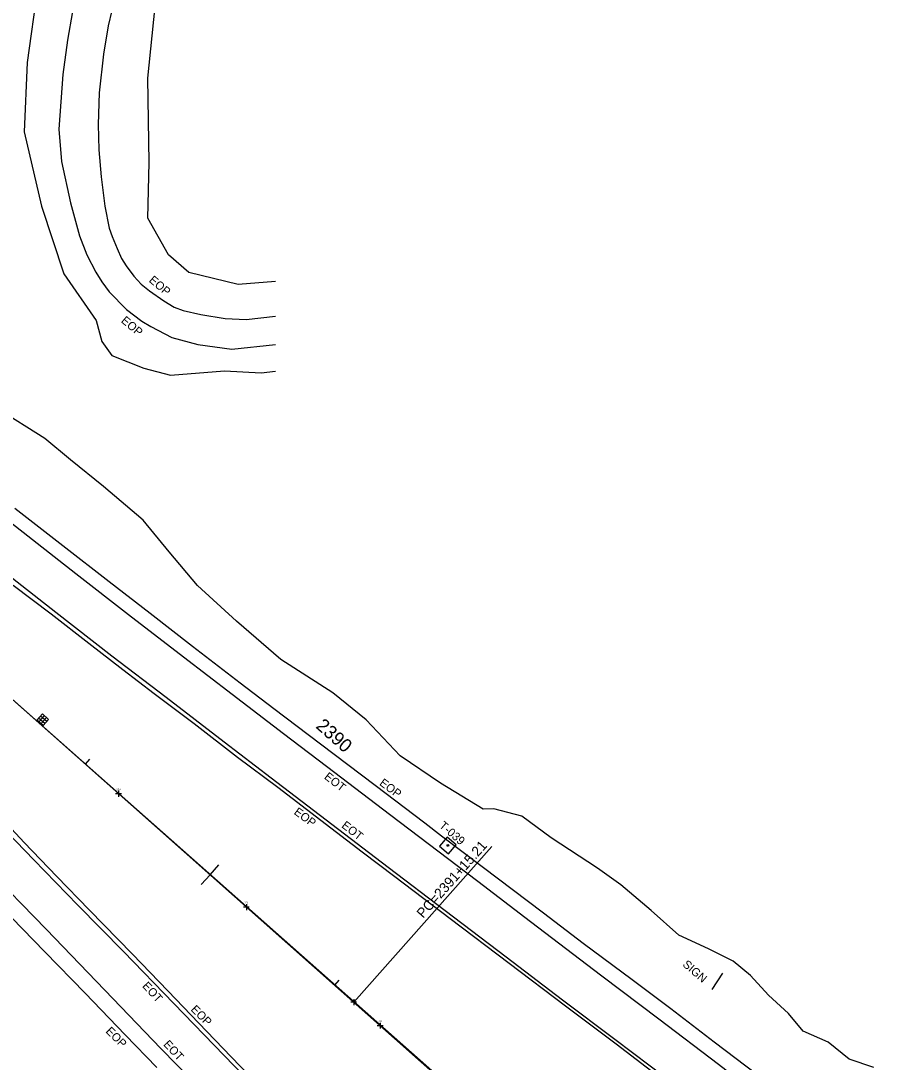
# Model space of a CAD drawing. Extents: x 2076109 to 2080761, y 592812 to 596750.
# Drawn here: x 2077729 to 2078257, y 595198 to 595823 of the extents above; entities that cross this region are included whole.
import ezdxf

# ---------------------------------------------------------------- set-up
doc = ezdxf.new("R2010")
doc.units = 0
for name, color, linetype in [('Default', 7, 'Continuous'), ('RD_EX_BldgApp', 7, 'Continuous'), ('RD_EX_BldgApp_txCode', 7, 'Continuous'), ('RD_EX_DR_Inlet', 7, 'Continuous'), ('RD_EX_Misc', 7, 'Continuous'), ('RD_EX_Misc_txCode', 7, 'Continuous'), ('RD_EX_Road', 7, 'Continuous'), ('RD_EX_Road_txCode', 7, 'Continuous'), ('RD_EX_VEG', 7, 'Continuous'), ('RD_HC_Cl', 7, 'Continuous'), ('RD_HC_Data', 7, 'Continuous'), ('RD_HC_Data_Tic', 7, 'Continuous'), ('RD_HC_Survey', 7, 'Continuous'), ('RD_HC_Survey_txCode', 7, 'Continuous'), ('RD_HC_TX_Sta50', 7, 'Continuous')]:
    doc.layers.add(name, color=color, linetype=linetype)

msp = doc.modelspace()

# ---------------------------------------------------------------- linework, layer by layer
at = {"layer": 'Default'}
for p, q in [((2077364.31, 595733.06), (2078453.96, 594769.07)), ((2077364.31, 595733.06), (2078453.96, 594769.07)), ((2077404.89, 595698.18), (2078420.27, 594797.03)), ((2077404.89, 595698.18), (2078420.27, 594797.03)), ((2077789.04, 595358.59), (2077785.54, 595358.59)), ((2077789.04, 595358.59), (2077785.54, 595358.59)), ((2077787.29, 595360.34), (2077787.29, 595356.84)), ((2077787.29, 595360.34), (2077787.29, 595356.84)), ((2077865.75, 595290.59), (2077862.25, 595290.59)), ((2077865.75, 595290.59), (2077862.25, 595290.59)), ((2077864, 595292.34), (2077864, 595288.84)), ((2077864, 595292.34), (2077864, 595288.84)), ((2077930.13, 595233.58), (2077926.63, 595233.58)), ((2077930.13, 595233.58), (2077926.63, 595233.58)), ((2077928.38, 595235.33), (2077928.38, 595231.83)), ((2077928.38, 595235.33), (2077928.38, 595231.83)), ((2077944.24, 595221.17), (2077944.24, 595217.67)), ((2077944.24, 595221.17), (2077944.24, 595217.67)), ((2077945.99, 595219.42), (2077942.49, 595219.42)), ((2077945.99, 595219.42), (2077942.49, 595219.42))]:
    msp.add_line(p, q, dxfattribs=at)
msp.add_arc((2104218.85, 624856.19), 39606.66, 228.410497, 230.313125, dxfattribs=at)
msp.add_arc((2104218.85, 624856.19), 39606.66, 228.410497, 230.313125, dxfattribs=at)
at = {"layer": 'RD_EX_BldgApp'}
msp.add_line((2078149.53, 595250.98), (2078143.14, 595241.23), dxfattribs=at)
msp.add_line((2078149.53, 595250.98), (2078143.14, 595241.23), dxfattribs=at)
at = {"layer": 'RD_EX_DR_Inlet'}
for p, q in [((2077743.08, 595400.72), (2077739.35, 595404.06)), ((2077743.08, 595400.72), (2077739.35, 595404.06)), ((2077742.81, 595405.53), (2077739.48, 595401.8)), ((2077742.81, 595405.53), (2077739.48, 595401.8)), ((2077744.21, 595401.99), (2077740.48, 595405.32)), ((2077744.21, 595401.99), (2077740.48, 595405.32)), ((2077744.08, 595404.39), (2077740.74, 595400.66)), ((2077744.08, 595404.39), (2077740.74, 595400.66))]:
    msp.add_line(p, q, dxfattribs=at)
msp.add_lwpolyline([(2077741.61, 595406.59), (2077745.34, 595403.26), (2077742.01, 595399.53), (2077738.28, 595402.86)], close=True, dxfattribs=at)
msp.add_lwpolyline([(2077741.61, 595406.59), (2077745.34, 595403.26), (2077742.01, 595399.53), (2077738.28, 595402.86)], close=True, dxfattribs=at)
at = {"layer": 'RD_EX_Misc'}
for points in [[(2077949.74, 595346.22), (2077917.12, 595371.24), (2077886.25, 595394.66), (2077855.54, 595418.26), (2077826.17, 595440.63), (2077793.37, 595466.01), (2077761.67, 595490.62), (2077722.71, 595521.26), (2077691.23, 595545.97), (2077665.74, 595566.25), (2077632.03, 595593.21), (2077582.35, 595633.88), (2077560.53, 595652.07), (2077526.26, 595680.98), (2077495.89, 595706.68), (2077469.6, 595728.93), (2077440.39, 595753.88), (2077413.8, 595776.66), (2077390.58, 595796.7)], [(2077949.74, 595346.22), (2077917.12, 595371.24), (2077886.25, 595394.66), (2077855.54, 595418.26), (2077826.17, 595440.63), (2077793.37, 595466.01), (2077761.67, 595490.62), (2077722.71, 595521.26), (2077691.23, 595545.97), (2077665.74, 595566.25), (2077632.03, 595593.21), (2077582.35, 595633.88), (2077560.53, 595652.07), (2077526.26, 595680.98), (2077495.89, 595706.68), (2077469.6, 595728.93), (2077440.39, 595753.88), (2077413.8, 595776.66), (2077390.58, 595796.7)], [(2077362.93, 595786.89), (2077392.15, 595761.97), (2077424.77, 595734), (2077441.81, 595719.44), (2077465.76, 595699.03), (2077496.26, 595672.94), (2077521.85, 595651.48), (2077549.58, 595628.1), (2077573.59, 595607.87), (2077599.85, 595586.33), (2077627.21, 595563.92), (2077661.18, 595537.05), (2077689.72, 595514.51), (2077716.09, 595493.76), (2077749.65, 595467.6), (2077783.36, 595441.51), (2077815.88, 595416.61), (2077850.74, 595389.82), (2077878.87, 595368.26), (2077915.16, 595340.49), (2077948.94, 595314.49)], [(2077362.93, 595786.89), (2077392.15, 595761.97), (2077424.77, 595734), (2077441.81, 595719.44), (2077465.76, 595699.03), (2077496.26, 595672.94), (2077521.85, 595651.48), (2077549.58, 595628.1), (2077573.59, 595607.87), (2077599.85, 595586.33), (2077627.21, 595563.92), (2077661.18, 595537.05), (2077689.72, 595514.51), (2077716.09, 595493.76), (2077749.65, 595467.6), (2077783.36, 595441.51), (2077815.88, 595416.61), (2077850.74, 595389.82), (2077878.87, 595368.26), (2077915.16, 595340.49), (2077948.94, 595314.49)], [(2077850.7, 595201.63), (2077820.53, 595232.8), (2077790.22, 595263.88), (2077762.8, 595291.76), (2077736.42, 595318.96), (2077709.92, 595346.36), (2077678.72, 595378.46), (2077649.91, 595408.22), (2077612.46, 595446.3), (2077577.19, 595481.07), (2077550.3, 595507.41), (2077509.12, 595546.77), (2077481.37, 595572.73), (2077443, 595608.1), (2077400.67, 595646.86), (2077373.88, 595670.82), (2077334.03, 595706.37), (2077304.56, 595732)], [(2077850.7, 595201.63), (2077820.53, 595232.8), (2077790.22, 595263.88), (2077762.8, 595291.76), (2077736.42, 595318.96), (2077709.92, 595346.36), (2077678.72, 595378.46), (2077649.91, 595408.22), (2077612.46, 595446.3), (2077577.19, 595481.07), (2077550.3, 595507.41), (2077509.12, 595546.77), (2077481.37, 595572.73), (2077443, 595608.1), (2077400.67, 595646.86), (2077373.88, 595670.82), (2077334.03, 595706.37), (2077304.56, 595732)], [(2077812.69, 595205.74), (2077779.15, 595240.73), (2077743.86, 595277.34), (2077707.16, 595314.93), (2077677.78, 595345.17), (2077641.95, 595381.51), (2077607.57, 595416.21), (2077570.67, 595452.82), (2077540.71, 595482.36), (2077500.4, 595521.29), (2077469.88, 595550.44), (2077431.8, 595585.6), (2077401.7, 595612.91), (2077373.73, 595637.96), (2077342.22, 595666.06), (2077323.28, 595683.05), (2077307.69, 595696.83), (2077294.47, 595708.58)], [(2077812.69, 595205.74), (2077779.15, 595240.73), (2077743.86, 595277.34), (2077707.16, 595314.93), (2077677.78, 595345.17), (2077641.95, 595381.51), (2077607.57, 595416.21), (2077570.67, 595452.82), (2077540.71, 595482.36), (2077500.4, 595521.29), (2077469.88, 595550.44), (2077431.8, 595585.6), (2077401.7, 595612.91), (2077373.73, 595637.96), (2077342.22, 595666.06), (2077323.28, 595683.05), (2077307.69, 595696.83), (2077294.47, 595708.58)], [(2078547.92, 594865.99), (2078523.55, 594887.48), (2078492.6, 594914.58), (2078461.72, 594941.03), (2078442.57, 594957.36), (2078414.55, 594981.01), (2078378.82, 595010.71), (2078326.85, 595053.48), (2078303.99, 595072.33), (2078272.31, 595097.98), (2078239.48, 595124.07), (2078206.94, 595149.86), (2078177.28, 595172.92), (2078147.14, 595196.07), (2078111.31, 595223.33), (2078077.15, 595249.21), (2078034.45, 595281.85), (2078002.89, 595305.93), (2077949.74, 595346.22)], [(2078547.92, 594865.99), (2078523.55, 594887.48), (2078492.6, 594914.58), (2078461.72, 594941.03), (2078442.57, 594957.36), (2078414.55, 594981.01), (2078378.82, 595010.71), (2078326.85, 595053.48), (2078303.99, 595072.33), (2078272.31, 595097.98), (2078239.48, 595124.07), (2078206.94, 595149.86), (2078177.28, 595172.92), (2078147.14, 595196.07), (2078111.31, 595223.33), (2078077.15, 595249.21), (2078034.45, 595281.85), (2078002.89, 595305.93), (2077949.74, 595346.22)], [(2077948.94, 595314.49), (2077983.17, 595288.64), (2078019.77, 595260.72), (2078053.66, 595234.89), (2078085.02, 595211.3), (2078116.87, 595187.29), (2078148.23, 595163.42), (2078181.8, 595137.39), (2078217.02, 595109.84), (2078246.55, 595086.19), (2078275.57, 595062.75), (2078305.1, 595038.73), (2078327.94, 595020.19), (2078351.12, 595001.07), (2078383.9, 594974.11), (2078414.8, 594947.69), (2078445.52, 594921.98), (2078475.27, 594896.22), (2078506.67, 594868.78), (2078527.36, 594850.61)], [(2077948.94, 595314.49), (2077983.17, 595288.64), (2078019.77, 595260.72), (2078053.66, 595234.89), (2078085.02, 595211.3), (2078116.87, 595187.29), (2078148.23, 595163.42), (2078181.8, 595137.39), (2078217.02, 595109.84), (2078246.55, 595086.19), (2078275.57, 595062.75), (2078305.1, 595038.73), (2078327.94, 595020.19), (2078351.12, 595001.07), (2078383.9, 594974.11), (2078414.8, 594947.69), (2078445.52, 594921.98), (2078475.27, 594896.22), (2078506.67, 594868.78), (2078527.36, 594850.61)], [(2077812.69, 595205.74), (2077860.4, 595156.88), (2077885.59, 595131.05), (2077918.9, 595096.93), (2077951.97, 595063.28), (2077986.45, 595028.54), (2078017.36, 594997.38), (2078046.97, 594968.42), (2078082.15, 594934.23), (2078115.46, 594902.77), (2078149.86, 594870.52), (2078195.91, 594828.19), (2078230.53, 594797.18), (2078270.78, 594762.03), (2078303.08, 594733.97), (2078349.76, 594694.22), (2078384.22, 594665.44)], [(2077812.69, 595205.74), (2077860.4, 595156.88), (2077885.59, 595131.05), (2077918.9, 595096.93), (2077951.97, 595063.28), (2077986.45, 595028.54), (2078017.36, 594997.38), (2078046.97, 594968.42), (2078082.15, 594934.23), (2078115.46, 594902.77), (2078149.86, 594870.52), (2078195.91, 594828.19), (2078230.53, 594797.18), (2078270.78, 594762.03), (2078303.08, 594733.97), (2078349.76, 594694.22), (2078384.22, 594665.44)], [(2078402.59, 594681.19), (2078376.88, 594702.6), (2078348.66, 594726.55), (2078315.84, 594754.87), (2078280.23, 594785.85), (2078257.02, 594806.28), (2078229.05, 594831.44), (2078194.83, 594862.11), (2078171.35, 594883.78), (2078139.88, 594913.53), (2078105.56, 594945.66), (2078078.38, 594971.9), (2078052.44, 594997.28), (2078024.89, 595024.02), (2077994.25, 595054.58), (2077968.94, 595080.1), (2077943.23, 595106.24), (2077919, 595131.04), (2077898.15, 595152.63), (2077868.92, 595182.73), (2077850.7, 595201.63)], [(2078402.59, 594681.19), (2078376.88, 594702.6), (2078348.66, 594726.55), (2078315.84, 594754.87), (2078280.23, 594785.85), (2078257.02, 594806.28), (2078229.05, 594831.44), (2078194.83, 594862.11), (2078171.35, 594883.78), (2078139.88, 594913.53), (2078105.56, 594945.66), (2078078.38, 594971.9), (2078052.44, 594997.28), (2078024.89, 595024.02), (2077994.25, 595054.58), (2077968.94, 595080.1), (2077943.23, 595106.24), (2077919, 595131.04), (2077898.15, 595152.63), (2077868.92, 595182.73), (2077850.7, 595201.63)]]:
    msp.add_lwpolyline(points, dxfattribs=at)
at = {"layer": 'RD_EX_Road'}
for points in [[(2077785.39, 595838.15), (2077781.1, 595819.63), (2077778.3, 595802.52), (2077775.75, 595779.35), (2077774.99, 595760.42), (2077775.46, 595745.15), (2077776.85, 595728.99), (2077779.01, 595711.45), (2077781.76, 595698.18), (2077783.47, 595693.15), (2077786.42, 595685.88), (2077789.1, 595679.93), (2077791.9, 595675.63), (2077796.45, 595669.39), (2077800.88, 595664.63), (2077805.85, 595660.61), (2077814.52, 595654.46), (2077820.76, 595650.75), (2077826.1, 595648.71), (2077836.65, 595646.4), (2077851.2, 595643.83), (2077863.79, 595643.28), (2077881.43, 595645.33)], [(2077785.39, 595838.15), (2077781.1, 595819.63), (2077778.3, 595802.52), (2077775.75, 595779.35), (2077774.99, 595760.42), (2077775.46, 595745.15), (2077776.85, 595728.99), (2077779.01, 595711.45), (2077781.76, 595698.18), (2077783.47, 595693.15), (2077786.42, 595685.88), (2077789.1, 595679.93), (2077791.9, 595675.63), (2077796.45, 595669.39), (2077800.88, 595664.63), (2077805.85, 595660.61), (2077814.52, 595654.46), (2077820.76, 595650.75), (2077826.1, 595648.71), (2077836.65, 595646.4), (2077851.2, 595643.83), (2077863.79, 595643.28), (2077881.43, 595645.33)], [(2077759.66, 595828.2), (2077756.72, 595810.93), (2077753.84, 595790.48), (2077751.51, 595757.53), (2077753.08, 595738.1), (2077758.38, 595713.3), (2077763.95, 595693.6), (2077768.24, 595682.16), (2077773.69, 595671.66), (2077777.2, 595665.93), (2077781.64, 595659.88), (2077792.03, 595649.24), (2077801.18, 595642.24), (2077806.57, 595639.05), (2077819.17, 595632.43), (2077834.77, 595628.29), (2077855.2, 595625.52), (2077881.39, 595628.28)], [(2077759.66, 595828.2), (2077756.72, 595810.93), (2077753.84, 595790.48), (2077751.51, 595757.53), (2077753.08, 595738.1), (2077758.38, 595713.3), (2077763.95, 595693.6), (2077768.24, 595682.16), (2077773.69, 595671.66), (2077777.2, 595665.93), (2077781.64, 595659.88), (2077792.03, 595649.24), (2077801.18, 595642.24), (2077806.57, 595639.05), (2077819.17, 595632.43), (2077834.77, 595628.29), (2077855.2, 595625.52), (2077881.39, 595628.28)], [(2077970.95, 595340.99), (2077941.15, 595363.54), (2077908.39, 595388.37), (2077880.38, 595409.68), (2077860.33, 595425.09), (2077831.72, 595447.1), (2077806.21, 595466.75), (2077781.68, 595485.77), (2077753.88, 595507.5), (2077725.13, 595529.95)], [(2077970.95, 595340.99), (2077941.15, 595363.54), (2077908.39, 595388.37), (2077880.38, 595409.68), (2077860.33, 595425.09), (2077831.72, 595447.1), (2077806.21, 595466.75), (2077781.68, 595485.77), (2077753.88, 595507.5), (2077725.13, 595529.95)], [(2077724.01, 595483.86), (2077746.81, 595466.67), (2077769.51, 595448.94), (2077789.94, 595433.21), (2077808.71, 595418.8), (2077832.68, 595400.85), (2077858.69, 595380.59), (2077882.81, 595362.61), (2077908.59, 595342.88), (2077933.38, 595323.73), (2077952.98, 595309.03)], [(2077724.01, 595483.86), (2077746.81, 595466.67), (2077769.51, 595448.94), (2077789.94, 595433.21), (2077808.71, 595418.8), (2077832.68, 595400.85), (2077858.69, 595380.59), (2077882.81, 595362.61), (2077908.59, 595342.88), (2077933.38, 595323.73), (2077952.98, 595309.03)], [(2077854.91, 595200.66), (2077835.52, 595221.02), (2077816.84, 595240.33), (2077795.72, 595262.34), (2077769.68, 595288.92), (2077750.23, 595309.06), (2077730.76, 595329.44), (2077715.27, 595345.72)], [(2077854.91, 595200.66), (2077835.52, 595221.02), (2077816.84, 595240.33), (2077795.72, 595262.34), (2077769.68, 595288.92), (2077750.23, 595309.06), (2077730.76, 595329.44), (2077715.27, 595345.72)], [(2078558.22, 594869.34), (2078530.91, 594893.2), (2078521.67, 594901.52), (2078497.33, 594922.45), (2078478.18, 594939.06), (2078452.82, 594960.76), (2078430.65, 594979.76), (2078394.66, 595009.49), (2078368.3, 595031.41), (2078336.81, 595057.13), (2078304.21, 595083.71), (2078270.36, 595111.03), (2078240.97, 595134.51), (2078202.89, 595164.59), (2078170.15, 595190.09), (2078144.69, 595209.49), (2078118.53, 595229.54), (2078095.36, 595247.04), (2078066.11, 595268.74), (2078042.16, 595286.91), (2078005.38, 595314.83), (2077980.94, 595333.23), (2077970.95, 595340.99)], [(2078558.22, 594869.34), (2078530.91, 594893.2), (2078521.67, 594901.52), (2078497.33, 594922.45), (2078478.18, 594939.06), (2078452.82, 594960.76), (2078430.65, 594979.76), (2078394.66, 595009.49), (2078368.3, 595031.41), (2078336.81, 595057.13), (2078304.21, 595083.71), (2078270.36, 595111.03), (2078240.97, 595134.51), (2078202.89, 595164.59), (2078170.15, 595190.09), (2078144.69, 595209.49), (2078118.53, 595229.54), (2078095.36, 595247.04), (2078066.11, 595268.74), (2078042.16, 595286.91), (2078005.38, 595314.83), (2077980.94, 595333.23), (2077970.95, 595340.99)], [(2077952.98, 595309.03), (2077986.31, 595283.86), (2078021.67, 595256.91), (2078055.44, 595231.27), (2078085.91, 595208.57), (2078127.78, 595176.36), (2078162.35, 595149.71), (2078195.51, 595123.85), (2078224.64, 595100.6), (2078250.87, 595079.67), (2078280.9, 595055.74), (2078317.56, 595025.94), (2078349.29, 594999.96), (2078375.78, 594977.71), (2078405, 594953.04), (2078440.35, 594923.16), (2078465.28, 594901.73), (2078507.59, 594865.01), (2078528.26, 594846.85)], [(2077952.98, 595309.03), (2077986.31, 595283.86), (2078021.67, 595256.91), (2078055.44, 595231.27), (2078085.91, 595208.57), (2078127.78, 595176.36), (2078162.35, 595149.71), (2078195.51, 595123.85), (2078224.64, 595100.6), (2078250.87, 595079.67), (2078280.9, 595055.74), (2078317.56, 595025.94), (2078349.29, 594999.96), (2078375.78, 594977.71), (2078405, 594953.04), (2078440.35, 594923.16), (2078465.28, 594901.73), (2078507.59, 594865.01), (2078528.26, 594846.85)], [(2077723.07, 595284.36), (2077743.1, 595263.78), (2077767.2, 595238.89), (2077791.25, 595213.98), (2077810.19, 595194.32)], [(2077723.07, 595284.36), (2077743.1, 595263.78), (2077767.2, 595238.89), (2077791.25, 595213.98), (2077810.19, 595194.32)], [(2077854.91, 595200.66), (2077877.75, 595177.1), (2077904.18, 595149.75), (2077928.86, 595124.99), (2077955.23, 595098.06), (2077983.95, 595068.48), (2078009.65, 595042.17), (2078033.35, 595018.7), (2078066.05, 594986.67), (2078092.96, 594960.65), (2078117.38, 594937.31), (2078149.5, 594907.79), (2078199.33, 594861.59), (2078231.01, 594833.12), (2078268.85, 594798.92), (2078297.2, 594774.26), (2078324.57, 594750.57), (2078355.73, 594723.65), (2078382.01, 594701.63), (2078403.91, 594683.55)], [(2077854.91, 595200.66), (2077877.75, 595177.1), (2077904.18, 595149.75), (2077928.86, 595124.99), (2077955.23, 595098.06), (2077983.95, 595068.48), (2078009.65, 595042.17), (2078033.35, 595018.7), (2078066.05, 594986.67), (2078092.96, 594960.65), (2078117.38, 594937.31), (2078149.5, 594907.79), (2078199.33, 594861.59), (2078231.01, 594833.12), (2078268.85, 594798.92), (2078297.2, 594774.26), (2078324.57, 594750.57), (2078355.73, 594723.65), (2078382.01, 594701.63), (2078403.91, 594683.55)]]:
    msp.add_lwpolyline(points, dxfattribs=at)
at = {"layer": 'RD_EX_VEG'}
for points in [[(2077881.48, 595666.18), (2077859.01, 595664.31), (2077829.44, 595671.5), (2077817.19, 595682.23), (2077804.91, 595704.21), (2077805.61, 595737.62), (2077804.88, 595788.24), (2077809.18, 595831.11), (2077816.84, 595876.65), (2077833.48, 595917.17), (2077847.66, 595951.31), (2077863.18, 595990.93), (2077867.34, 596006.71), (2077881.56, 596023.72), (2077895.2, 596030.93), (2077937.59, 596053.88)], [(2077881.48, 595666.18), (2077859.01, 595664.31), (2077829.44, 595671.5), (2077817.19, 595682.23), (2077804.91, 595704.21), (2077805.61, 595737.62), (2077804.88, 595788.24), (2077809.18, 595831.11), (2077816.84, 595876.65), (2077833.48, 595917.17), (2077847.66, 595951.31), (2077863.18, 595990.93), (2077867.34, 596006.71), (2077881.56, 596023.72), (2077895.2, 596030.93), (2077937.59, 596053.88)], [(2077738.76, 595842.17), (2077732.42, 595797.53), (2077730.71, 595755.97), (2077741.09, 595711.34), (2077754.53, 595670.74), (2077773.79, 595642.67), (2077777.22, 595630.21), (2077783.21, 595621.65), (2077802.45, 595614.19), (2077818.44, 595609.85), (2077850.78, 595612.44), (2077872.78, 595611.28), (2077881.36, 595612.26)], [(2077738.76, 595842.17), (2077732.42, 595797.53), (2077730.71, 595755.97), (2077741.09, 595711.34), (2077754.53, 595670.74), (2077773.79, 595642.67), (2077777.22, 595630.21), (2077783.21, 595621.65), (2077802.45, 595614.19), (2077818.44, 595609.85), (2077850.78, 595612.44), (2077872.78, 595611.28), (2077881.36, 595612.26)], [(2077980.47, 595364.96), (2077956.15, 595381.36), (2077935.83, 595402.97), (2077915.86, 595419.13), (2077884.72, 595439.23), (2077858.01, 595462.2), (2077834.73, 595483.56), (2077817.71, 595503.85), (2077801.99, 595522.85), (2077778.19, 595543.17), (2077758.44, 595559.15), (2077743.14, 595571.92), (2077714.37, 595589.83)], [(2077980.47, 595364.96), (2077956.15, 595381.36), (2077935.83, 595402.97), (2077915.86, 595419.13), (2077884.72, 595439.23), (2077858.01, 595462.2), (2077834.73, 595483.56), (2077817.71, 595503.85), (2077801.99, 595522.85), (2077778.19, 595543.17), (2077758.44, 595559.15), (2077743.14, 595571.92), (2077714.37, 595589.83)], [(2078240.36, 595194.3), (2078225.66, 595199.27), (2078213.01, 595209.48), (2078198.06, 595216.12), (2078189.26, 595226.73), (2078177.14, 595237.78), (2078166.35, 595249.52), (2078156.02, 595258.13), (2078141.12, 595265.47), (2078123.36, 595273.77), (2078106.87, 595288.53), (2078088.53, 595303.94), (2078074.7, 595314.05), (2078046.8, 595332.26), (2078029.16, 595345.25), (2078012.5, 595349.66), (2078005.97, 595349.33), (2077980.47, 595364.96)], [(2078240.36, 595194.3), (2078225.66, 595199.27), (2078213.01, 595209.48), (2078198.06, 595216.12), (2078189.26, 595226.73), (2078177.14, 595237.78), (2078166.35, 595249.52), (2078156.02, 595258.13), (2078141.12, 595265.47), (2078123.36, 595273.77), (2078106.87, 595288.53), (2078088.53, 595303.94), (2078074.7, 595314.05), (2078046.8, 595332.26), (2078029.16, 595345.25), (2078012.5, 595349.66), (2078005.97, 595349.33), (2077980.47, 595364.96)]]:
    msp.add_lwpolyline(points, dxfattribs=at)
at = {"layer": 'RD_HC_Cl'}
msp.add_line((2077404.89, 595698.18), (2077928.38, 595233.58), dxfattribs=at)
msp.add_line((2077404.89, 595698.18), (2077928.38, 595233.58), dxfattribs=at)
msp.add_arc((2104218.85, 624856.19), 39606.66, 228.410497, 230.313125, dxfattribs=at)
msp.add_arc((2104218.85, 624856.19), 39606.66, 228.410497, 230.313125, dxfattribs=at)
at = {"layer": 'RD_HC_Data'}
msp.add_line((2077928.38, 595233.58), (2078011.27, 595326.98), dxfattribs=at)
msp.add_line((2077928.38, 595233.58), (2078011.27, 595326.98), dxfattribs=at)
at = {"layer": 'RD_HC_Data_Tic'}
for p, q in [((2077767.42, 595376.44), (2077770.07, 595379.43)), ((2077767.42, 595376.44), (2077770.07, 595379.43)), ((2077842.21, 595310.06), (2077847.52, 595316.04)), ((2077842.21, 595310.06), (2077847.52, 595316.04)), ((2077842.21, 595310.06), (2077836.9, 595304.08)), ((2077842.21, 595310.06), (2077836.9, 595304.08)), ((2077917, 595243.68), (2077919.66, 595246.67)), ((2077917, 595243.68), (2077919.66, 595246.67))]:
    msp.add_line(p, q, dxfattribs=at)
at = {"layer": 'RD_HC_Survey'}
msp.add_lwpolyline([(2077989.86, 595327.95), (2077984.51, 595332.58), (2077979.88, 595327.23), (2077985.23, 595322.6)], close=True, dxfattribs=at)
msp.add_lwpolyline([(2077989.86, 595327.95), (2077984.51, 595332.58), (2077979.88, 595327.23), (2077985.23, 595322.6)], close=True, dxfattribs=at)
msp.add_circle((2077984.87, 595327.59), 0.5, dxfattribs=at)
msp.add_circle((2077984.87, 595327.59), 0.5, dxfattribs=at)

# ---------------------------------------------------------------- texts
at = {"layer": 'Default'}
for s, p in [('229', (2077786.11, 595360.79)), ('229', (2077786.11, 595360.79)), ('230', (2077862.78, 595292.79)), ('230', (2077862.78, 595292.79)), ('231', (2077943.34, 595221.62)), ('231', (2077943.34, 595221.62))]:
    msp.add_text(s, height=1, dxfattribs=at).set_placement(p)
at = {"layer": 'RD_EX_BldgApp_txCode'}
msp.add_text('SIGN', height=5, rotation=319.16753, dxfattribs=at).set_placement((2078125.29, 595255.54))
msp.add_text('SIGN', height=5, rotation=319.16753, dxfattribs=at).set_placement((2078125.29, 595255.54))
at = {"layer": 'RD_EX_Misc_txCode'}
for rotation, p in [(322.17288, (2077910.25, 595368.05)), (322.17288, (2077910.25, 595368.05)), (322.17288, (2077920.67, 595338.79)), (322.17288, (2077920.67, 595338.79)), (312.70531, (2077801.21, 595243)), (312.70531, (2077801.21, 595243)), (312.70531, (2077813.89, 595207.96)), (312.70531, (2077813.89, 595207.96))]:
    msp.add_text('EOT', height=5, rotation=rotation, dxfattribs=at).set_placement(p)
at = {"layer": 'RD_EX_Road_txCode'}
for rotation, p in [(319.75923, (2077805.13, 595666.29)), (319.75923, (2077805.13, 595666.29)), (319.75923, (2077788.43, 595642)), (319.75923, (2077788.43, 595642)), (323.33303, (2077943.38, 595364.22)), (323.33303, (2077943.38, 595364.22)), (323.33303, (2077892.09, 595346.81)), (323.33303, (2077892.09, 595346.81)), (314.73234, (2077830.29, 595228.84)), (314.73234, (2077830.29, 595228.84)), (314.73234, (2077779.25, 595215.73)), (314.73234, (2077779.25, 595215.73))]:
    msp.add_text('EOP', height=5, rotation=rotation, dxfattribs=at).set_placement(p)
at = {"layer": 'RD_HC_Data'}
msp.add_text('PC=2391+15.21', height=6, rotation=48.4105, dxfattribs=at).set_placement((2077970.03, 595283.53))
msp.add_text('PC=2391+15.21', height=6, rotation=48.4105, dxfattribs=at).set_placement((2077970.03, 595283.53))
at = {"layer": 'RD_HC_Survey_txCode'}
msp.add_text('T-039', height=5, rotation=319.16753, dxfattribs=at).set_placement((2077979.21, 595338.89))
msp.add_text('T-039', height=5, rotation=319.16753, dxfattribs=at).set_placement((2077979.21, 595338.89))
at = {"layer": 'RD_HC_TX_Sta50'}
msp.add_text('2390', height=8, rotation=318.4105, dxfattribs=at).set_placement((2077905.17, 595398.58))
msp.add_text('2390', height=8, rotation=318.4105, dxfattribs=at).set_placement((2077905.17, 595398.58))

doc.saveas('drawing.dxf')
